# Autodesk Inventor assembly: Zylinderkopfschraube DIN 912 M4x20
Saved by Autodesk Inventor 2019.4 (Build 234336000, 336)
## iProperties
Created: 2021-06
Part Number: Zylinderkopfschraube DIN 912 M4x20
Document SubType Name: Assembly
Designer: Administrator
Title: Zylinderkopfschraube DIN 912 M4x20 v2
Author: Administrator
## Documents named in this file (2)
- c:\worker\convert-fusion-r04\tmp\job-1\39\output\files\e1e84fd7-b652-4e3d-a1c7-f0a54bbc30a7\Zylinderkopfschraube DIN 912 M4x20 v2_3.iam
- c:\worker\convert-fusion-r04\tmp\job-1\39\output\files\e1e84fd7-b652-4e3d-a1c7-f0a54bbc30a7\HI_WUERTH 00824  20 cylinder head screw DIN 912 M4x20 8.8 BLK.ipt
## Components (1 placed, 1 different names)
1. HI_WUERTH 00824  20 cylinder head screw DIN 912 M4x20 8.8 BLK:1
